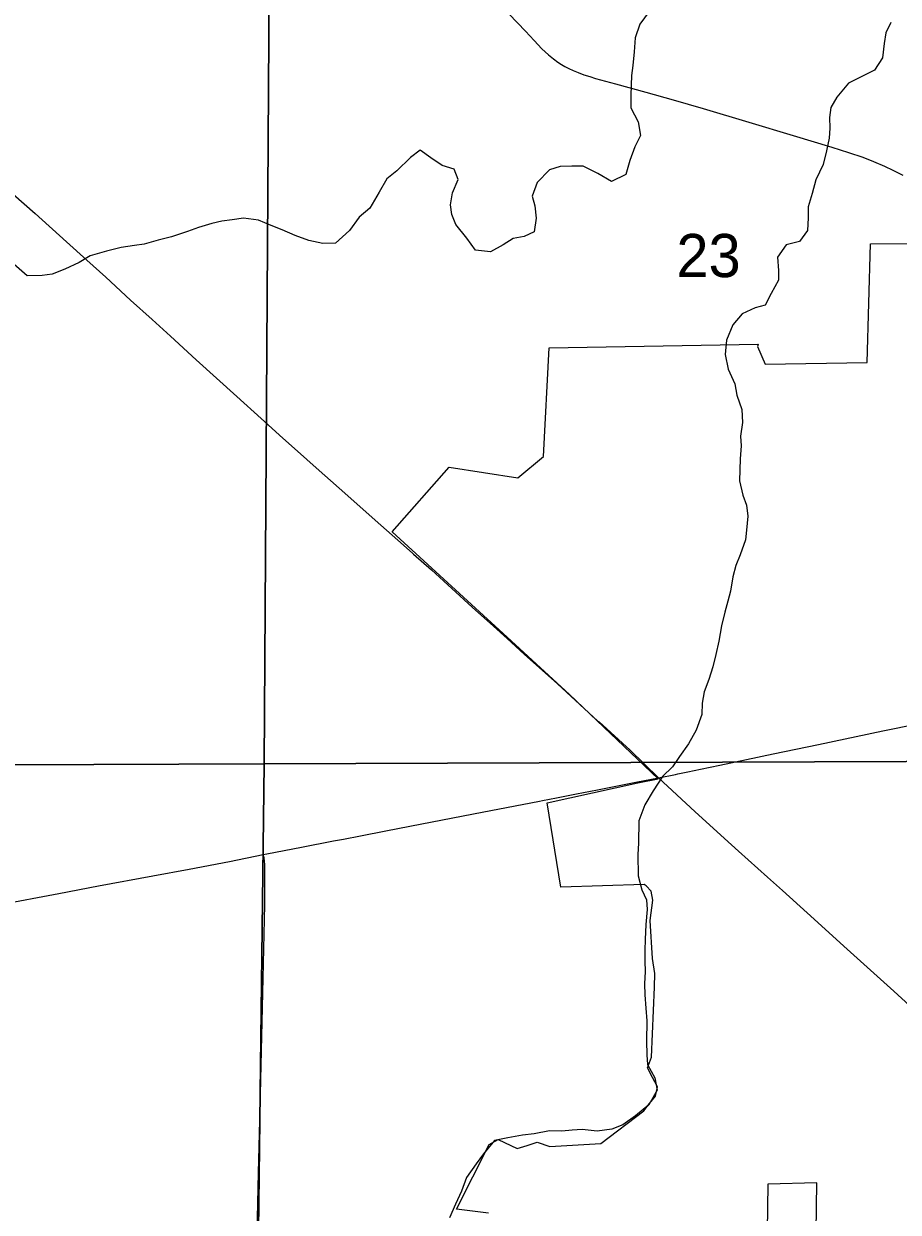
# Model space of a CAD drawing. Extents: x 0 to 34, y 0 to 22.
# Drawn here: x 4.352 to 4.775, y 18.195 to 18.771 of the extents above; entities that cross this region are included whole.
import ezdxf

# ---------------------------------------------------------------- set-up
doc = ezdxf.new("R2010")
doc.units = 0
for name, color, linetype in [('GM_X_Corporation', 7, 'Continuous'), ('GM_X_County_Road', 7, 'Continuous'), ('GM_X_Minor_River', 7, 'Continuous'), ('GM_X_Section', 7, 'Continuous'), ('GM_X_Section_Text', 7, 'Continuous'), ('GM_X_State_Route', 7, 'Continuous'), ('GM_X_US_Route', 7, 'Continuous')]:
    doc.layers.add(name, color=color, linetype=linetype)

msp = doc.modelspace()

# ---------------------------------------------------------------- linework, layer by layer
at = {"layer": 'GM_X_Corporation'}
for points in [[(4.57691, 18.19456), (4.56139, 18.19654), (4.57735, 18.22784), (4.5817, 18.23021), (4.59078, 18.2259), (4.59569, 18.2274), (4.6006, 18.2289), (4.60665, 18.22685), (4.63131, 18.22836), (4.65225, 18.24419), (4.65503, 18.24768), (4.6578, 18.25117), (4.65883, 18.25581), (4.65644, 18.26035), (4.65405, 18.26489), (4.656, 18.27006), (4.65743, 18.30408), (4.65757, 18.31071), (4.65635, 18.31799), (4.65533, 18.33643), (4.65662, 18.34619), (4.65568, 18.35064), (4.65332, 18.35323), (4.6524, 18.35381), (4.61195, 18.35254), (4.60542, 18.39332), (4.64928, 18.40304), (4.65914, 18.40497), (4.61613, 18.44593), (4.58594, 18.4736), (4.53038, 18.52476), (4.55788, 18.55612), (4.59116, 18.55089), (4.60356, 18.56117), (4.60632, 18.61385), (4.70763, 18.61561), (4.70732, 18.61452), (4.71097, 18.60591), (4.76047, 18.60679), (4.76193, 18.66434), (4.84625, 18.66485)], [(4.73532, 18.16158), (4.73596, 18.20919), (4.71227, 18.20866), (4.71197, 18.18573)]]:
    msp.add_lwpolyline(points, dxfattribs=at)
at = {"layer": 'GM_X_County_Road'}
for points in [[(4.57889, 18.78411), (4.59481, 18.7673), (4.59909, 18.76282), (4.60287, 18.75887), (4.60599, 18.75591), (4.60837, 18.75395), (4.6106, 18.75232), (4.61237, 18.75118), (4.61402, 18.75024), (4.61595, 18.74921), (4.61797, 18.74827), (4.62035, 18.74728), (4.62311, 18.74625), (4.62607, 18.74531), (4.62878, 18.74449), (4.63854, 18.74189), (4.65322, 18.7378), (4.66637, 18.73407), (4.68101, 18.72987), (4.70307, 18.72333), (4.72449, 18.71685), (4.74324, 18.71118), (4.75137, 18.70862), (4.75832, 18.70624), (4.76342, 18.70423), (4.76885, 18.70192), (4.7728, 18.70004), (4.77765, 18.69765)], [(4.46428, 18.1603), (4.46451, 18.16997), (4.46555, 18.21408), (4.46644, 18.25212), (4.4676, 18.30134), (4.4686, 18.34398), (4.46864, 18.36173), (4.4686, 18.36356), (4.46846, 18.36513), (4.46824, 18.36681), (4.46782, 18.36829)]]:
    msp.add_lwpolyline(points, dxfattribs=at)
at = {"layer": 'GM_X_Minor_River'}
for points in [[(4.65485, 18.77696), (4.65025, 18.77073), (4.64793, 18.7641), (4.6475, 18.75728), (4.64688, 18.75064), (4.64628, 18.7459), (4.64583, 18.73642), (4.64597, 18.73015), (4.64953, 18.72349), (4.65062, 18.71684), (4.64792, 18.71135), (4.64541, 18.70473), (4.64346, 18.69792), (4.63661, 18.69455), (4.62999, 18.6984), (4.62281, 18.70187), (4.61731, 18.70191), (4.61161, 18.70176), (4.60648, 18.70009), (4.60055, 18.69406), (4.59804, 18.68744), (4.59933, 18.68269), (4.60005, 18.6768), (4.59905, 18.67017), (4.59429, 18.66792), (4.58897, 18.66683), (4.58402, 18.66383), (4.57792, 18.66046), (4.57072, 18.66127), (4.56639, 18.66699), (4.56113, 18.67367), (4.55927, 18.67843), (4.55854, 18.68318), (4.55954, 18.68906), (4.56224, 18.69549), (4.56038, 18.70044), (4.55451, 18.70219), (4.54903, 18.70602), (4.54394, 18.70967), (4.53917, 18.7061), (4.53248, 18.69969), (4.52771, 18.69575), (4.52406, 18.68932), (4.51945, 18.68158), (4.51429, 18.67725), (4.50969, 18.67083), (4.50282, 18.66462), (4.49674, 18.66448), (4.48992, 18.66586), (4.4833, 18.66838), (4.47706, 18.67108), (4.47176, 18.67321), (4.46552, 18.67572), (4.45832, 18.67672), (4.45281, 18.676), (4.44787, 18.67528), (4.44293, 18.67418), (4.43646, 18.67214), (4.43114, 18.67028), (4.42334, 18.66768), (4.41688, 18.66603), (4.41022, 18.66418), (4.40547, 18.66345), (4.39902, 18.66255), (4.39198, 18.66071), (4.384, 18.65849), (4.37866, 18.65531), (4.37181, 18.65194), (4.36553, 18.64952), (4.36078, 18.64899), (4.35357, 18.64885), (4.34697, 18.6544)], [(4.77188, 18.77153), (4.76938, 18.76661), (4.76858, 18.7613), (4.76777, 18.75448), (4.76393, 18.74844), (4.75136, 18.74208), (4.74562, 18.73529), (4.74274, 18.73038), (4.74213, 18.72545), (4.74229, 18.72032), (4.74206, 18.71558), (4.74069, 18.70933), (4.73912, 18.7027), (4.73546, 18.69533), (4.73371, 18.6887), (4.73177, 18.68226), (4.73173, 18.67695), (4.73149, 18.67069), (4.72766, 18.66541), (4.7212, 18.66375), (4.71698, 18.6579), (4.7175, 18.65144), (4.71747, 18.6467), (4.71382, 18.64028), (4.71093, 18.6346), (4.70618, 18.63331), (4.69989, 18.63032), (4.6953, 18.62504), (4.69221, 18.61767), (4.69159, 18.61065), (4.69306, 18.60362), (4.69623, 18.59639), (4.69733, 18.59088), (4.69975, 18.58403), (4.70008, 18.57776), (4.69909, 18.57113), (4.69943, 18.56638), (4.69882, 18.56013), (4.69878, 18.55481), (4.69855, 18.5495), (4.70021, 18.54247), (4.70188, 18.53771), (4.7026, 18.53239), (4.70198, 18.52557), (4.70138, 18.52083), (4.69886, 18.51364), (4.69673, 18.50834), (4.69537, 18.50285), (4.69418, 18.49603), (4.69282, 18.4911), (4.69145, 18.4858), (4.68988, 18.47917), (4.6885, 18.47178), (4.68713, 18.46534), (4.68556, 18.45928), (4.68362, 18.45322), (4.68149, 18.44717), (4.6805, 18.44167), (4.68027, 18.43617), (4.67756, 18.4286), (4.67391, 18.42199), (4.6695, 18.41576), (4.66605, 18.41085)], [(4.66605, 18.41085), (4.66127, 18.40614), (4.65667, 18.39916), (4.65264, 18.39236), (4.64973, 18.3846), (4.64966, 18.37378), (4.64924, 18.36828), (4.64954, 18.35804), (4.6512, 18.35119), (4.65344, 18.34643), (4.65379, 18.34169), (4.65317, 18.33448), (4.65292, 18.32708), (4.6527, 18.32196), (4.65266, 18.31665), (4.65281, 18.31171), (4.65258, 18.30564), (4.65273, 18.30033), (4.65325, 18.29387), (4.65359, 18.2878), (4.65352, 18.27793), (4.65366, 18.27129), (4.654, 18.26655), (4.65756, 18.26007), (4.65866, 18.25418), (4.65462, 18.247), (4.64813, 18.24173), (4.64203, 18.23741), (4.6367, 18.23518), (4.62967, 18.23428), (4.62228, 18.23509), (4.61753, 18.23475), (4.61241, 18.23422), (4.60653, 18.23445), (4.59912, 18.23299), (4.59342, 18.23227), (4.58639, 18.231), (4.57993, 18.22972), (4.57457, 18.22331), (4.57093, 18.2184), (4.56633, 18.2118), (4.56381, 18.20517), (4.56092, 18.19893), (4.55803, 18.19231)]]:
    msp.add_lwpolyline(points, dxfattribs=at)
at = {"layer": 'GM_X_Section'}
for points in [[(3.98059, 18.9165), (4.47149, 18.91545), (4.46827, 18.41225), (3.9728, 18.4103)], [(4.47149, 18.91545), (4.96887, 18.91739), (4.95692, 18.41406), (4.46827, 18.41225)], [(4.95692, 18.41406), (4.95614, 17.90875), (4.46218, 17.9068), (4.46827, 18.41225)], [(4.46827, 18.41225), (4.46218, 17.9068), (3.96579, 17.90789), (3.9728, 18.4103)]]:
    msp.add_lwpolyline(points, close=True, dxfattribs=at)
at = {"layer": 'GM_X_State_Route'}
for points in [[(4.3414, 18.69304), (4.35732, 18.67903), (4.3725, 18.6653), (4.38238, 18.65644), (4.39158, 18.64807), (4.40359, 18.63706), (4.414, 18.62764), (4.42289, 18.61959), (4.43535, 18.608), (4.45498, 18.59032), (4.46681, 18.57963), (4.47736, 18.57012), (4.48442, 18.5638), (4.4935, 18.55579), (4.50461, 18.54588), (4.51027, 18.54089), (4.52208, 18.53037), (4.53577, 18.51833), (4.54036, 18.51422), (4.54068, 18.51394)], [(4.54068, 18.51394), (4.54931, 18.50624), (4.56909, 18.48824), (4.57934, 18.47903)], [(4.57934, 18.47903), (4.58599, 18.47307), (4.59434, 18.4653), (4.60874, 18.45246), (4.61034, 18.45103), (4.63, 18.43303), (4.6305, 18.43257)], [(4.67358, 18.40842), (4.67966, 18.4097), (4.68896, 18.41165), (4.7149, 18.41717), (4.73681, 18.42172), (4.768, 18.4282), (4.78472, 18.43173), (4.78513, 18.43182), (4.79632, 18.43422), (4.81482, 18.43845), (4.82872, 18.44169), (4.83947, 18.44414), (4.85404, 18.44736)], [(4.6305, 18.43257), (4.64551, 18.41893), (4.65937, 18.40553)], [(4.66868, 18.40739), (4.67358, 18.40842)], [(4.65937, 18.40553), (4.66748, 18.40713), (4.66868, 18.40739)]]:
    msp.add_lwpolyline(points, dxfattribs=at)
at = {"layer": 'GM_X_US_Route'}
for points in [[(4.60992, 18.39585), (4.61966, 18.39774), (4.62973, 18.3997), (4.64344, 18.40242), (4.64909, 18.40352)], [(4.64909, 18.40352), (4.65937, 18.40553)], [(4.65937, 18.40553), (4.67715, 18.38897), (4.69467, 18.37302)], [(4.50667, 18.37585), (4.51501, 18.37745), (4.52723, 18.37974), (4.54461, 18.38318), (4.57388, 18.38894), (4.60166, 18.39425), (4.60307, 18.39452)], [(4.60307, 18.39452), (4.60992, 18.39585)], [(4.33948, 18.34389), (4.3688, 18.34937), (4.38803, 18.35309), (4.41432, 18.35793), (4.43204, 18.36125), (4.45157, 18.36497), (4.46782, 18.36829), (4.46954, 18.36864), (4.48632, 18.37193), (4.50188, 18.37494), (4.50667, 18.37585)], [(4.69467, 18.37302), (4.69807, 18.36993), (4.71213, 18.35729)], [(4.71213, 18.35729), (4.71934, 18.35082), (4.7314, 18.34005), (4.75067, 18.32244), (4.7733, 18.30206), (4.79993, 18.27774), (4.8101, 18.2686), (4.83556, 18.24561)]]:
    msp.add_lwpolyline(points, dxfattribs=at)

# ---------------------------------------------------------------- texts
at = {"layer": 'GM_X_Section_Text'}
msp.add_text('23', height=0.020928, rotation=0.00001, dxfattribs=at).set_placement((4.66799, 18.64816))

doc.saveas('drawing.dxf')
